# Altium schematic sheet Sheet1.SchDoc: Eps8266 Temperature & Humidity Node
size A4; Engineer: Evert; Revision: 1.0; SheetNumber: 1; SheetTotal: 1
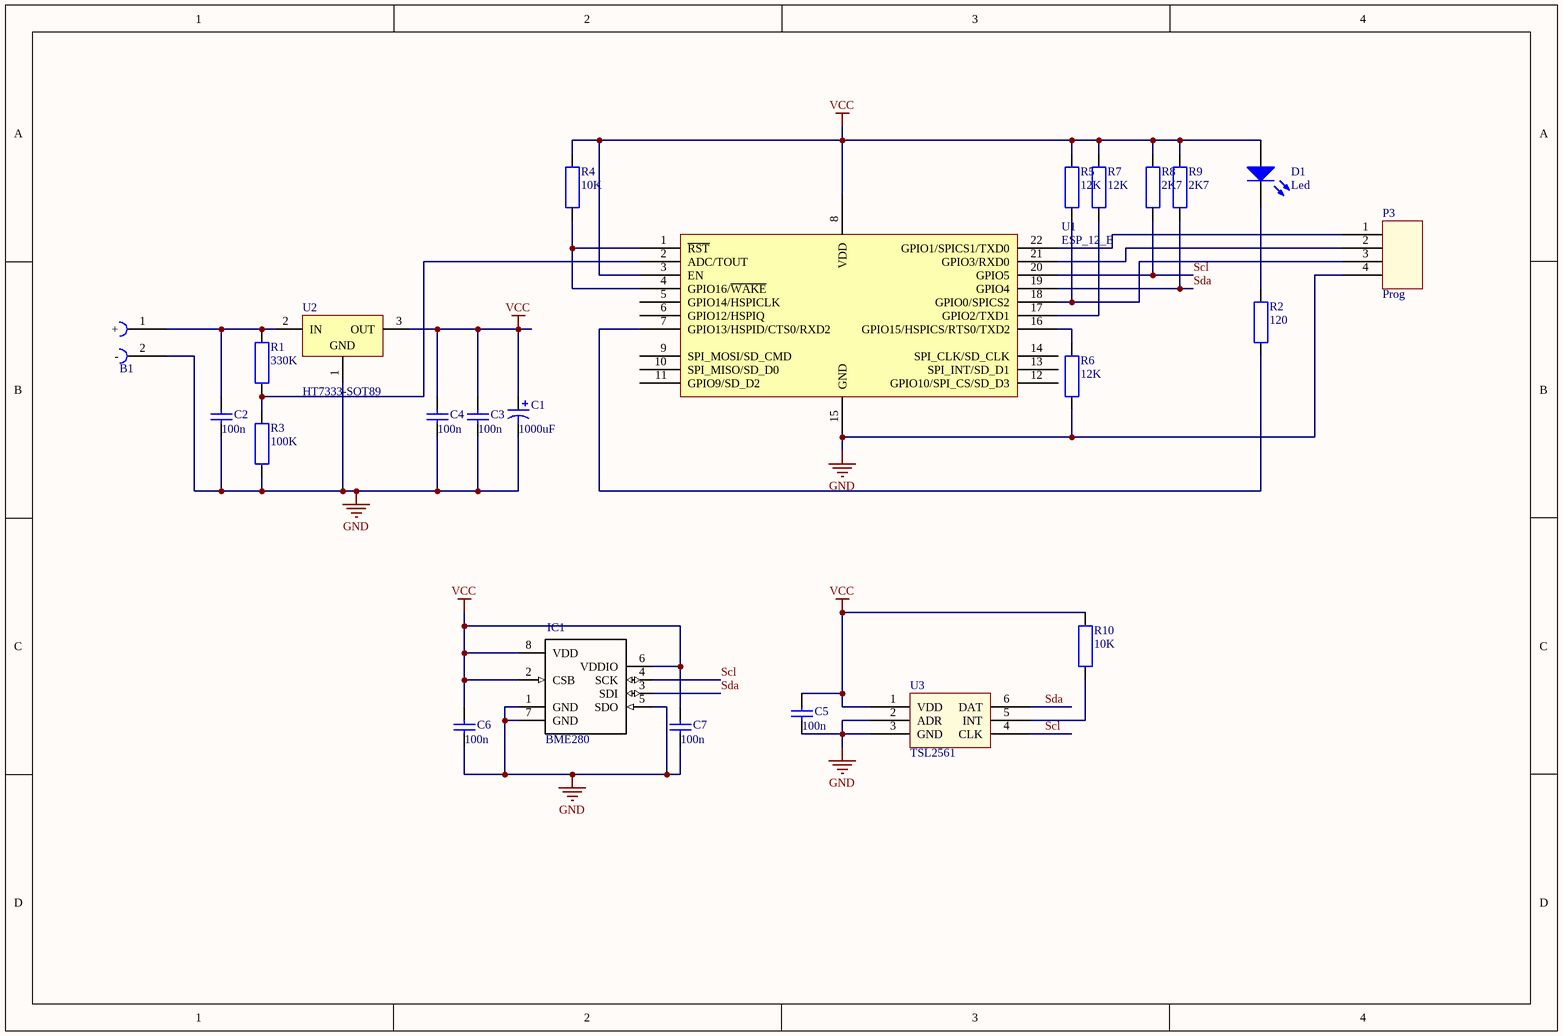
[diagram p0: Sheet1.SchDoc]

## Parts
B1  KeyStone54  [Keystone54_18650]  (value not drawn)
C1  value 1000uF  [X]  (hidden comment: T491X)
C2  value 100n  [1608[0603]]  (hidden comment: Cap Semi)
C3  value 100n  [1608[0603]]  (hidden comment: Cap Semi)
C4  value 100n  [1608[0603]]  (hidden comment: Cap Semi)
C5  value 100n  [1608[0603]]  (hidden comment: Cap Semi)
C6  value 100n  [1608[0603]]  (hidden comment: Cap Semi)
C7  value 100n  [1608[0603]]  (hidden comment: Cap Semi)
D1  Led  [LED1608]
IC1  BME280  [BME280]
P3  Prog  [Header4x1.27mm]
R1  value 330K  [RES0603R]  (hidden comment: Resistor)
R2  value 120  [RES0603R]  (hidden comment: Resistor)
R3  value 100K  [RES0603R]  (hidden comment: Resistor)
R4  value 10K  [RES0603R]  (hidden comment: Resistor)
R5  value 12K  [RES0603R]  (hidden comment: Resistor)
R6  value 12K  [RES0603R]  (hidden comment: Resistor)
R7  value 12K  [RES0603R]  (hidden comment: Resistor)
R8  value 2K7  [RES0603R]  (hidden comment: Resistor)
R9  value 2K7  [RES0603R]  (hidden comment: Resistor)
R10  value 10K  [RES0603R]  (hidden comment: Resistor)
U1  ESP_12_E  [ESP_12_E]
U2  HT7333-SOT89  [SOT89_N]
U3  TSL2561  [DFN6-2x2]

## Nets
GND: B1.2(-) C1.2 C2.1 C3.1 C4.1 C5.1 C6.1 C7.1 IC1.1(GND) IC1.5(SDO) IC1.7(GND) P3.4 R3.2 R6.2 U1.15(GND) U2.1(GND) U3.2(ADR) U3.3(GND)
VCC: C1.1 C3.2 C4.2 C5.2 C6.2 C7.2 D1.1(A) IC1.2(CSB) IC1.6(VDDIO) IC1.8(VDD) R4.1 R5.1 R7.1 R8.1 R9.1 R10.1 U1.3(EN) U1.8(VDD) U2.3(OUT) U3.1(VDD)
Scl: IC1.4(SCK) R8.2 U1.20(GPIO5) U3.4(CLK)
Sda: IC1.3(SDI) R9.2 U1.19(GPIO4) U3.6(DAT)
NetB1_1: B1.1(+) C2.2 R1.1 U2.2(IN)
NetD1_2: D1.2(K) R2.1
NetP3_1: P3.1 U1.22(GPIO1/SPICS1/TXD0)
NetP3_2: P3.2 U1.21(GPIO3/RXD0)
NetP3_3: P3.3 R5.2 U1.18(GPIO0/SPICS2)
NetR1_2: R1.2 R3.1 U1.2(ADC/TOUT)
NetR2_2: R2.2 U1.7(GPIO13/HSPID/CTS0/RXD2)
NetR4_2: R4.2 U1.1(~{RST}) U1.4(GPIO16/~{WAKE})
NetR6_1: R6.1 U1.16(GPIO15/HSPICS/RTS0/TXD2)
NetR7_2: R7.2 U1.17(GPIO2/TXD1)
NetR10_2: R10.2 U3.5(INT)

Not connected (* = marked no-connect by the designer): U1 5(GPIO14/HSPICLK) 6(GPIO12/HSPIQ) 9(SPI_MOSI/SD_CMD) 10(SPI_MISO/SD_D0) 11(GPIO9/SD_D2) 12(GPIO10/SPI_CS/SD_D3) 13(SPI_INT/SD_D1) 14(SPI_CLK/SD_CLK)

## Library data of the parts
C1 = T491X: Solid Tantalum Chip Capacitor, Standard T491 Series - Industrial Grade; PCB_Layout: Round Glue Pad at 2.9 ±0.1mm in diameter at KEMET's option
C2-C7 = Cap Semi: Capacitor (Semiconductor SIM Model)
D1 = Led: pin to pad: 1>A 2>K
IC1 = BME280: Integrated pressure, humidity and temperature sensor; 8-pin 2.5x2.5x0.93mm LGA; MF: Bosch
P3 = Header4x1.27mm
U1 = ESP_12_E: ESP-12 Wi-Fi Module by AI-Thinker; IC: ESP8266-EX
U2 = HT7333-SOT89: Low Power Consumption LDO, Output Voltage 3.3V, SOT89 Pkg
